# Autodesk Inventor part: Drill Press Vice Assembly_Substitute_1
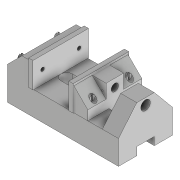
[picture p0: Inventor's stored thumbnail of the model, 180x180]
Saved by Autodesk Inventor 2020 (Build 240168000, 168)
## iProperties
Created: 2019-08
Part Number: Drill Press Vice Assembly_Substitute_1
Material: Generic
Document SubType Name: Modeling
Designer: LENOVO-CADCIM
Density: 1 g/cm^3
Appearance: Default
Author: LENOVO-CADCIM
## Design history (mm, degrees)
derived "Drill Press Vice Assembly.iam"
body "Solid1"
node "Base.ipt:1"
node "Jaw Face.ipt:1"
body "Solid2"
node "Movable Jaw.ipt:1"
body "Solid3"
node "Jaw Face.ipt:2"
body "Solid4"
node "Cap Screw.ipt:1"
body "Solid5"
node "Cap Screw.ipt:2"
body "Solid6"
node "Cap Screw.ipt:3"
body "Solid7"
node "Cap Screw.ipt:4"
body "Solid8"
